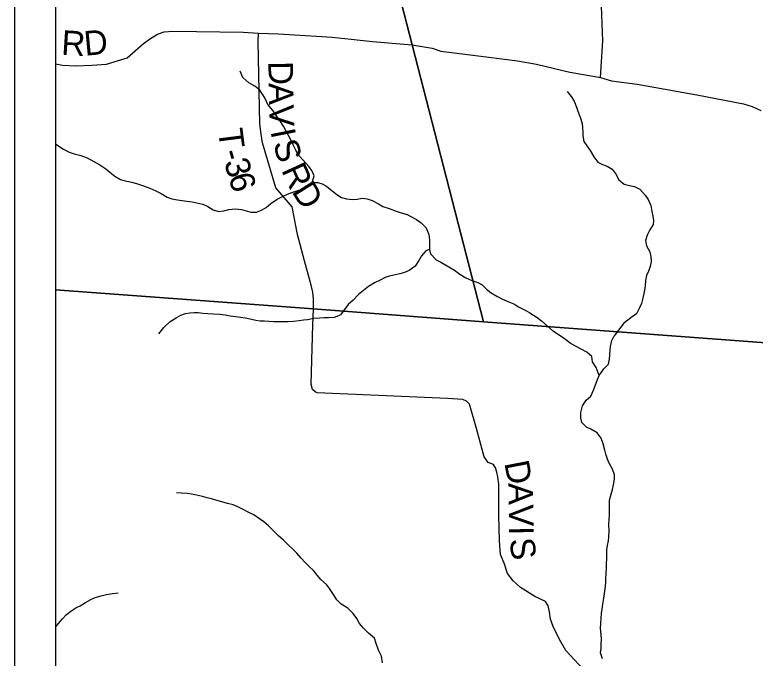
# Model space of a CAD drawing. Extents: x 0 to 34, y 0 to 22.
# Drawn here: x 2.106 to 3.817, y 18.581 to 20.069 of the extents above; entities that cross this region are included whole.
import ezdxf

# ---------------------------------------------------------------- set-up
doc = ezdxf.new("R2010")
doc.units = 0
for name, color, linetype in [('Default', 7, 'Continuous'), ('GM_X_County_Road', 7, 'Continuous'), ('GM_X_County_Road_Text', 7, 'Continuous'), ('GM_X_Minor_River', 7, 'Continuous'), ('GM_X_Township_Road', 7, 'Continuous'), ('GM_X_Township_Road_Text', 7, 'Continuous'), ('SH_Cut_Line', 7, 'Continuous')]:
    doc.layers.add(name, color=color, linetype=linetype)

msp = doc.modelspace()

# ---------------------------------------------------------------- linework, layer by layer
at = {"layer": 'Default'}
for points in [[(9.087, 13.8822), (2.1062, 13.8822), (2.1062, 20.9054), (9.087, 20.9054)], [(2.8183, 20.8), (2.2, 20.8), (2.2, 19.4329), (2.7961, 19.3885), (3.1893, 19.3592), (3.0244, 19.9995)], [(5.8621, 20.8), (2.8183, 20.8), (3.0244, 19.9995), (3.1893, 19.3592), (4.7641, 19.2419), (4.831, 19.2363), (5.1554, 19.2083), (5.1782, 19.2598), (5.5496, 20.1004), (5.5679, 20.1313), (5.5783, 20.1528), (5.5834, 20.1771), (5.5869, 20.1933), (5.5951, 20.2127), (5.6047, 20.2229), (5.6166, 20.2359)]]:
    msp.add_lwpolyline(points, close=True, dxfattribs=at)
msp.add_lwpolyline([(4.7194, 16.7424), (4.6758, 16.8903), (4.9207, 17.3435), (4.9239, 17.3511), (4.937, 17.4953), (4.9996, 18.0806), (5.0018, 18.1008), (4.7661, 18.9124), (4.831, 19.2363), (4.7641, 19.2419), (3.1893, 19.3592), (2.7961, 19.3885), (2.2, 19.4329), (2.2, 14)], dxfattribs=at)
at = {"layer": 'GM_X_County_Road'}
for points in [[(2.2, 19.9555), (2.2166, 19.9525), (2.2465, 19.9506), (2.2841, 19.9519), (2.3179, 19.9547), (2.3656, 19.9689), (2.4038, 20.0027), (2.42, 20.0136), (2.4361, 20.0241), (2.4515, 20.0293), (2.4726, 20.031), (2.6342, 20.0288), (2.6698, 20.0266), (2.7155, 20.0246), (2.7526, 20.0223), (2.8034, 20.0191), (2.8396, 20.0173), (2.8836, 20.0127), (2.9332, 20.007), (2.9966, 20.0019), (3.0246, 19.999), (3.0387, 19.9967)], [(3.0387, 19.9967), (3.0709, 19.9913), (3.0911, 19.985), (3.1959, 19.9712), (3.2678, 19.9623), (3.312, 19.9545), (3.3342, 19.9493), (3.3892, 19.9361), (3.4204, 19.9307), (3.4596, 19.9234), (3.4855, 19.9157), (3.5446, 19.908), (3.6829, 19.8833), (3.7901, 19.8625), (3.8106, 19.8567), (3.8307, 19.8474)]]:
    msp.add_lwpolyline(points, dxfattribs=at)
at = {"layer": 'GM_X_Minor_River'}
for points in [[(2.7939, 19.6807), (2.7983, 19.6962), (2.7924, 19.7084), (2.786, 19.718), (2.773, 19.7329), (2.7636, 19.7425), (2.7559, 19.7555), (2.7499, 19.7677), (2.7452, 19.7784), (2.7385, 19.7899), (2.7333, 19.7998), (2.727, 19.8109), (2.7188, 19.8242), (2.7107, 19.8353), (2.7036, 19.8464), (2.6913, 19.8617), (2.6847, 19.8755), (2.6791, 19.885), (2.6724, 19.8946), (2.6612, 19.9034), (2.6473, 19.9116), (2.6334, 19.9235), (2.6268, 19.9387)], [(3.3832, 19.8912), (3.3922, 19.88), (3.3992, 19.869), (3.4047, 19.8552), (3.4073, 19.8457), (3.4128, 19.832), (3.4172, 19.8172), (3.4182, 19.8077), (3.4188, 19.7982), (3.4191, 19.7887), (3.4216, 19.7758), (3.4283, 19.7658), (3.4357, 19.7547), (3.4442, 19.7406), (3.4536, 19.728), (3.4648, 19.7225), (3.4757, 19.7186), (3.487, 19.712), (3.4959, 19.6994), (3.5015, 19.6883), (3.5146, 19.6772), (3.527, 19.6744), (3.5383, 19.6716), (3.5508, 19.6654), (3.5631, 19.6519), (3.5701, 19.6416), (3.576, 19.6275), (3.5789, 19.6142), (3.581, 19.6032), (3.5824, 19.5933), (3.5816, 19.5838), (3.5739, 19.5718), (3.5677, 19.5589), (3.5637, 19.5472), (3.5662, 19.5347), (3.5736, 19.5209), (3.5765, 19.5099), (3.5772, 19.4981), (3.5751, 19.4868), (3.5705, 19.4758), (3.5662, 19.466), (3.5642, 19.4547), (3.5629, 19.4414), (3.5608, 19.4285), (3.558, 19.4138), (3.5545, 19.4009), (3.5502, 19.3911), (3.5429, 19.3775), (3.5333, 19.3701), (3.5234, 19.3626), (3.5139, 19.3555), (3.4918, 19.3264)], [(2.2, 19.7707), (2.2077, 19.765), (2.2189, 19.758), (2.2317, 19.7514), (2.2438, 19.7475), (2.2592, 19.7431), (2.2735, 19.7377), (2.2889, 19.7299), (2.3025, 19.7222), (2.3164, 19.7129), (2.3261, 19.7052), (2.3373, 19.6956), (2.3505, 19.6878), (2.3614, 19.6847), (2.3765, 19.6815), (2.3897, 19.6779), (2.404, 19.6732), (2.4187, 19.6677), (2.4322, 19.6615), (2.4446, 19.6556), (2.4585, 19.6467), (2.4691, 19.6436), (2.4826, 19.6411), (2.4932, 19.6395), (2.5042, 19.6382), (2.5159, 19.6362), (2.5298, 19.633), (2.5408, 19.6306), (2.5524, 19.6255), (2.5648, 19.6174), (2.578, 19.6138), (2.5897, 19.6152), (2.6007, 19.6185), (2.6163, 19.6202), (2.6299, 19.6185), (2.6408, 19.6154), (2.6525, 19.6126), (2.6649, 19.6124), (2.6767, 19.6172), (2.6874, 19.6232), (2.6981, 19.6322), (2.7129, 19.6422), (2.7266, 19.6496), (2.7365, 19.6541), (2.7464, 19.6578), (2.7604, 19.6625), (2.7707, 19.6658), (2.7802, 19.6691), (2.7939, 19.6807), (2.8064, 19.6813), (2.8166, 19.6778), (2.8264, 19.6728), (2.8361, 19.6651), (2.8503, 19.6535), (2.8616, 19.6465), (2.8729, 19.643), (2.8865, 19.6417), (2.8975, 19.6427), (2.91, 19.6445), (2.9209, 19.6436), (2.9322, 19.6393), (2.9469, 19.6319), (2.9566, 19.6257), (2.9717, 19.621), (2.9879, 19.6147), (2.9992, 19.6112), (3.0128, 19.6068), (3.0229, 19.6018), (3.0349, 19.5952), (3.0458, 19.5875), (3.057, 19.5763), (3.0633, 19.5607), (3.065, 19.5486), (3.0645, 19.5368), (3.0648, 19.5262), (3.0669, 19.5163), (3.0804, 19.5021), (3.0909, 19.4967), (3.1097, 19.4858), (3.1228, 19.4785), (3.1348, 19.4692), (3.1487, 19.4603), (3.1622, 19.4541), (3.1762, 19.4494), (3.1863, 19.4443), (3.1968, 19.4347), (3.2073, 19.4259), (3.2204, 19.4178), (3.2336, 19.4115), (3.2494, 19.4045), (3.261, 19.3994), (3.2708, 19.3936), (3.2862, 19.3855), (3.2967, 19.3797), (3.3132, 19.3685), (3.3234, 19.3615)], [(3.0648, 19.5262), (3.056, 19.5229), (3.0461, 19.5116), (3.0402, 19.5003), (3.0318, 19.4875), (3.0177, 19.4774), (3.007, 19.473), (2.9964, 19.4701), (2.9824, 19.4665), (2.9725, 19.4643), (2.9623, 19.4614), (2.9505, 19.4554), (2.9379, 19.4491), (2.9235, 19.4402), (2.912, 19.4309), (2.9009, 19.4219), (2.8879, 19.4091), (2.8765, 19.399), (2.859, 19.3751)], [(2.4393, 19.3307), (2.4503, 19.3455), (2.4655, 19.3596), (2.4792, 19.3683), (2.4902, 19.374), (2.5008, 19.3782), (2.5106, 19.3793), (2.5209, 19.3801), (2.5304, 19.3801), (2.541, 19.379), (2.5527, 19.3778), (2.5653, 19.3771), (2.5801, 19.3763), (2.5926, 19.3748), (2.6039, 19.3729), (2.6161, 19.371), (2.629, 19.3695), (2.6434, 19.3672), (2.6536, 19.3653), (2.6631, 19.363), (2.673, 19.3615), (2.6832, 19.3611), (2.6931, 19.3607), (2.7044, 19.3599), (2.7173, 19.3596), (2.7382, 19.3596), (2.7503, 19.3603), (2.7636, 19.3622), (2.7735, 19.3634), (2.783, 19.3645), (2.7974, 19.3672), (2.8103, 19.3683), (2.8216, 19.3687), (2.8315, 19.3687), (2.8448, 19.3698), (2.859, 19.3751)], [(3.3234, 19.3615), (3.3505, 19.3373)], [(3.4569, 19.2348), (3.4497, 19.2535), (3.4413, 19.2664), (3.4398, 19.2785), (3.4285, 19.2888), (3.4156, 19.296), (3.4023, 19.3029), (3.3898, 19.3097), (3.3761, 19.32), (3.3655, 19.3272), (3.3505, 19.3373)], [(3.4642, 18.5799), (3.4596, 18.5932), (3.4611, 18.6039), (3.4615, 18.6145), (3.4623, 18.6244), (3.4615, 18.6362), (3.46, 18.6506), (3.4604, 18.6616), (3.4615, 18.6734), (3.4623, 18.6844), (3.4638, 18.6947), (3.4657, 18.7057), (3.468, 18.7198), (3.4695, 18.7304), (3.4707, 18.7415), (3.4722, 18.7551), (3.4726, 18.7647), (3.4733, 18.7768), (3.4737, 18.7894), (3.4741, 18.7996), (3.4745, 18.8114), (3.4745, 18.8217), (3.4749, 18.8315), (3.4764, 18.8418), (3.4783, 18.8525), (3.4795, 18.862), (3.4798, 18.8749), (3.4791, 18.8901), (3.4802, 18.9022), (3.481, 18.9121), (3.481, 18.9228), (3.4806, 18.9368), (3.481, 18.9463), (3.4844, 18.9604), (3.4875, 18.971), (3.4898, 18.9821), (3.492, 18.995), (3.4924, 19.0053), (3.4875, 19.0182), (3.4807, 19.0307), (3.4761, 19.041), (3.472, 19.0528), (3.4697, 19.0623), (3.4663, 19.0767), (3.4614, 19.09), (3.4519, 19.1022), (3.4375, 19.1105), (3.4276, 19.1151), (3.4166, 19.1261), (3.4144, 19.1368), (3.4144, 19.1493), (3.4182, 19.1645), (3.4265, 19.1774), (3.4379, 19.1866), (3.444, 19.201), (3.4474, 19.2105), (3.4527, 19.2253), (3.4569, 19.2348), (3.4675, 19.25), (3.4785, 19.2611), (3.4808, 19.2725), (3.4815, 19.2827), (3.4823, 19.2926), (3.4831, 19.3021), (3.4865, 19.3158), (3.4918, 19.3264)], [(2.5044, 18.9616), (2.4911, 18.9628), (2.4797, 18.9631)], [(2.9559, 18.5701), (2.954, 18.586), (2.9465, 18.5993), (2.9415, 18.6153), (2.9374, 18.6271), (2.9241, 18.6389), (2.912, 18.6503), (2.9032, 18.6613), (2.8968, 18.6727), (2.8885, 18.6845), (2.8756, 18.697), (2.8604, 18.7062), (2.8506, 18.7157), (2.8445, 18.7263), (2.8335, 18.7419), (2.8263, 18.7514), (2.8134, 18.7632), (2.8047, 18.7734), (2.7967, 18.7837), (2.7865, 18.7928), (2.777, 18.802), (2.7683, 18.8122), (2.7577, 18.8236), (2.7486, 18.8331), (2.7372, 18.8438), (2.7262, 18.8548), (2.7167, 18.8632), (2.7046, 18.8746), (2.6929, 18.8871), (2.6819, 18.8966), (2.672, 18.9034), (2.6587, 18.9122), (2.647, 18.9183), (2.6326, 18.9259), (2.622, 18.9308), (2.6106, 18.9354), (2.5981, 18.9388), (2.5844, 18.9426), (2.5711, 18.9468), (2.5605, 18.9495), (2.551, 18.9517), (2.5404, 18.9548), (2.5264, 18.9578), (2.5143, 18.9601), (2.5044, 18.9616)], [(2.2, 18.6531), (2.2073, 18.661), (2.2156, 18.6712), (2.2255, 18.6819), (2.2357, 18.6895), (2.2471, 18.6975), (2.257, 18.7024), (2.2699, 18.71), (2.282, 18.7169), (2.2923, 18.7214), (2.3059, 18.7252), (2.3184, 18.7283), (2.3317, 18.7305), (2.345, 18.732)]]:
    msp.add_lwpolyline(points, dxfattribs=at)
at = {"layer": 'GM_X_Township_Road'}
for points in [[(3.4596, 19.9234), (3.4653, 20.0088), (3.4608, 20.1294), (3.46, 20.1696)], [(2.7963, 19.388), (2.7968, 19.4116), (2.7947, 19.4274), (2.7911, 19.4434), (2.7756, 19.5002), (2.7599, 19.5604), (2.7473, 19.6246), (2.7098, 19.6684), (2.6787, 19.7729), (2.6753, 19.7929), (2.6724, 19.8169), (2.6687, 20.0072), (2.6698, 20.0266)], [(3.4202, 18.556), (3.3798, 18.5986), (3.3654, 18.6242), (3.3509, 18.6543), (3.3443, 18.6715), (3.3422, 18.6886), (3.3393, 18.7023), (3.333, 18.7119), (3.3082, 18.7239), (3.2751, 18.7448), (3.2583, 18.7601), (3.2448, 18.777), (3.2372, 18.8006), (3.2287, 18.8212), (3.2264, 18.8523), (3.2247, 18.9116), (3.2247, 18.9453), (3.2251, 18.9833), (3.2223, 19.0008), (3.2205, 19.011), (3.2174, 19.0211), (3.2124, 19.0287), (3.2003, 19.0336), (3.1912, 19.0465), (3.173, 19.1122), (3.1574, 19.1684), (3.1506, 19.1752), (3.1421, 19.1791), (3.1064, 19.1816), (2.8054, 19.1946), (2.8002, 19.1972), (2.794, 19.2024), (2.7914, 19.2143), (2.7919, 19.2428), (2.7952, 19.3522), (2.7963, 19.388)]]:
    msp.add_lwpolyline(points, dxfattribs=at)
at = {"layer": 'SH_Cut_Line'}
for points in [[(9, 18.8941), (9, 20.8), (2.2, 20.8), (2.2, 19.4329), (2.7961, 19.3885), (3.1893, 19.3592), (4.7641, 19.2419), (4.831, 19.2363), (5.1554, 19.2083), (5.3224, 19.1939), (5.8337, 19.1499), (6.226, 19.1161), (6.8442, 19.0679), (8.0305, 18.9725), (8.8762, 18.9027)], [(2.2, 19.4329), (2.2, 14), (9, 14), (9, 18.8941), (8.8762, 18.9027), (8.0305, 18.9725), (6.8442, 19.0679), (6.226, 19.1161), (5.8337, 19.1499), (5.3224, 19.1939), (5.1554, 19.2083), (4.831, 19.2363), (4.7641, 19.2419), (3.1893, 19.3592), (2.7961, 19.3885)]]:
    msp.add_lwpolyline(points, close=True, dxfattribs=at)

# ---------------------------------------------------------------- texts
at = {"layer": 'GM_X_County_Road_Text'}
for s, rotation, p in [('R', 356.4616, (2.2127, 19.9766)), ('D', 5.3207, (2.2687, 19.9739))]:
    msp.add_text(s, height=0.0568, rotation=rotation, dxfattribs=at).set_placement(p)
at = {"layer": 'GM_X_Township_Road_Text'}
for s, rotation, p in [('D', 270.9982, (2.6922, 19.9609)), ('A', 271.0093, (2.6931, 19.9109)), ('V', 271.9037, (2.694, 19.86)), ('T', 277.2404, (2.5757, 19.8026)), ('I', 281.3478, (2.6969, 19.7998)), ('S', 286.3749, (2.7027, 19.7717)), ('-', 286.249, (2.583, 19.7509)), ('3', 286.2449, (2.5895, 19.7285)), ('R', 294.6082, (2.7216, 19.7098)), ('6', 286.4569, (2.5994, 19.6947)), ('D', 302.3073, (2.745, 19.66)), ('D', 281.0142, (3.2373, 19.0327)), ('A', 271.5047, (3.2465, 18.9861)), ('V', 270.725, (3.2478, 18.9363)), ('I', 271.0342, (3.2485, 18.886)), ('S', 277.5734, (3.2494, 18.8556))]:
    msp.add_text(s, height=0.0568, rotation=rotation, dxfattribs=at).set_placement(p)

doc.saveas('drawing.dxf')
